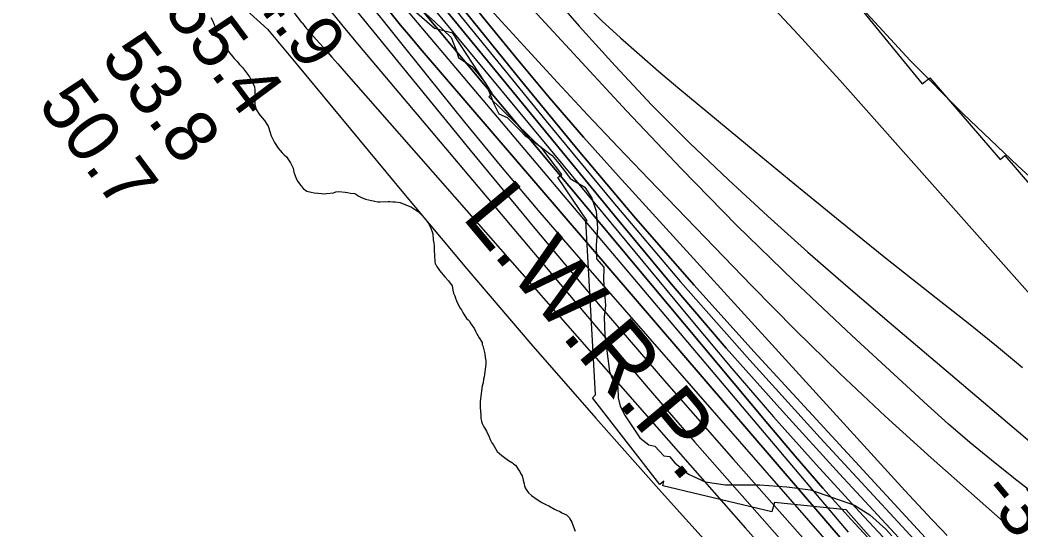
# Model space of a CAD drawing. Extents: x 3172231 to 3210228, y 940198 to 965780.
# Drawn here: x 3189862 to 3191136, y 947827 to 948476 of the extents above; entities that cross this region are included whole.
import ezdxf

# ---------------------------------------------------------------- set-up
doc = ezdxf.new("R2010")
doc.units = 0
for name, color, linetype in [('V-RIVR-EDGE', 7, 'Continuous'), ('V-RIVR-RANG', 7, 'Continuous'), ('V-RRAP-RVMT', 7, 'Continuous'), ('V-SITE-VEGE', 7, 'Continuous'), ('V-TOPO-DPTH', 7, 'Continuous'), ('V-TOPO-MAJR', 7, 'Continuous'), ('V-TOPO-MINR', 7, 'Continuous'), ('V-TOPO-WATR', 7, 'Continuous'), ('V-TOPO-WATR-IDEN', 7, 'Continuous')]:
    doc.layers.add(name, color=color, linetype=linetype)

msp = doc.modelspace()

# ---------------------------------------------------------------- linework, layer by layer
at = {"layer": 'V-RIVR-EDGE'}
msp.add_lwpolyline([(3190366.316, 948495.274), (3190390.12, 948473.951), (3190410.816, 948454.193), (3190416.484, 948439.139), (3190420.089, 948428.757), (3190437.175, 948417.305), (3190444.931, 948407.951), (3190454.754, 948395.48), (3190465.062, 948369.523), (3190471.255, 948357.061), (3190482.135, 948352.366), (3190499.205, 948334.691), (3190504.379, 948329.492), (3190513.18, 948323.247), (3190539.063, 948303.994), (3190547.854, 948293.599), (3190556.125, 948282.688), (3190562.328, 948274.375), (3190580.972, 948263.437), (3190589.753, 948249.413), (3190595.417, 948232.803), (3190596.921, 948211.536), (3190595.311, 948189.757), (3190595.786, 948172.123), (3190605.095, 948161.728), (3190604.536, 948145.133), (3190607.049, 948112.972), (3190605.456, 948097.936), (3190606.437, 948075.114), (3190612.028, 948028.943), (3190616.152, 948019.079), (3190622.869, 948008.69), (3190623.354, 947995.205), (3190625.921, 947984.826), (3190632.114, 947972.363), (3190650.715, 947944.312), (3190662.103, 947935.467), (3190669.878, 947933.892), (3190681.257, 947921.417), (3190688.515, 947920.362), (3190695.238, 947912.566), (3190712.835, 947898.001), (3190734.074, 947888.094), (3190759.996, 947884.4), (3190803.56, 947884.292), (3190837.784, 947882.133), (3190867.854, 947877.91), (3190923.817, 947858.582), (3190943.494, 947846.087), (3190963.675, 947827.885), (3190971.434, 947819.568)], dxfattribs=at)
at = {"layer": 'V-RRAP-RVMT'}
for p, q in [((3190389.336, 948465.465), (3190316.177, 948529.551)), ((3190928.391, 948495.235), (3191010.045, 948395.015)), ((3190413.033, 948459.827), (3190389.336, 948465.465)), ((3190462.729, 948383.048), (3190413.033, 948459.827)), ((3191010.045, 948395.015), (3191019.644, 948402.58)), ((3191019.644, 948402.58), (3191109.229, 948298.649)), ((3190458.678, 948378.482), (3190462.729, 948383.048)), ((3190527.429, 948311.44), (3190458.678, 948378.482)), ((3190551.491, 948279.665), (3190527.429, 948311.44)), ((3191109.229, 948298.649), (3191115.239, 948303.819)), ((3191115.239, 948303.819), (3191203.379, 948201.157)), ((3190546.232, 948275.951), (3190551.491, 948279.665)), ((3190583.935, 948220.607), (3190546.232, 948275.951)), ((3190594.437, 947999.217), (3190582.116, 948220.942)), ((3190582.116, 948220.942), (3190583.935, 948220.607)), ((3190590.752, 947995.233), (3190594.437, 947999.217)), ((3190676.421, 947884.906), (3190590.752, 947995.233)), ((3190681.229, 947889.042), (3190676.421, 947884.906)), ((3190680.041, 947883.411), (3190681.229, 947889.042)), ((3190818.891, 947849.985), (3190680.041, 947883.411)), ((3190822.343, 947861.93), (3190818.891, 947849.985)), ((3190913.183, 947852.785), (3190822.343, 947861.93)), ((3190998.585, 947756.725), (3190913.183, 947852.785))]:
    msp.add_line(p, q, dxfattribs=at)
at = {"layer": 'V-SITE-VEGE'}
for p, q in [((3190104.765, 948479.78), (3190106.871, 948475.696)), ((3190106.871, 948475.696), (3190108.949, 948470.511)), ((3190108.949, 948470.511), (3190110.305, 948465.71)), ((3190110.305, 948465.71), (3190113.4, 948456.83)), ((3190113.4, 948456.83), (3190114.448, 948454.604)), ((3190114.448, 948454.604), (3190117.608, 948448.661)), ((3190117.608, 948448.661), (3190121.881, 948443.058)), ((3190121.881, 948443.058), (3190132.938, 948429.59)), ((3190132.938, 948429.59), (3190134.353, 948427.353)), ((3190134.353, 948427.353), (3190138.299, 948423.593)), ((3190138.299, 948423.593), (3190141.515, 948419.848)), ((3190141.515, 948419.848), (3190145.095, 948416.096)), ((3190145.095, 948416.096), (3190153.987, 948404.146)), ((3190153.987, 948404.146), (3190157.147, 948398.2)), ((3190157.147, 948398.2), (3190160.301, 948391.89)), ((3190160.301, 948391.89), (3190160.915, 948386.74)), ((3190160.915, 948386.74), (3190160.768, 948380.505)), ((3190160.768, 948380.505), (3190161.03, 948376.096)), ((3190161.03, 948376.096), (3190160.858, 948368.76)), ((3190160.858, 948368.76), (3190162.546, 948362.485)), ((3190162.546, 948362.485), (3190166.443, 948356.523)), ((3190166.443, 948356.523), (3190170.371, 948352.028)), ((3190170.371, 948352.028), (3190173.22, 948348.292)), ((3190173.22, 948348.292), (3190175.342, 948344.942)), ((3190175.342, 948344.942), (3190177.822, 948341.215)), ((3190177.822, 948341.215), (3190180.199, 948333.086)), ((3190180.199, 948333.086), (3190181.574, 948329.019)), ((3190181.574, 948329.019), (3190183.327, 948325.676)), ((3190183.327, 948325.676), (3190185.772, 948320.481)), ((3190185.772, 948320.481), (3190190.378, 948313.403)), ((3190190.378, 948313.403), (3190195.74, 948307.406)), ((3190195.74, 948307.406), (3190198.246, 948304.779)), ((3190198.246, 948304.779), (3190201.12, 948302.145)), ((3190201.12, 948302.145), (3190206.447, 948294.682)), ((3190206.447, 948294.682), (3190209.582, 948287.637)), ((3190209.582, 948287.637), (3190210.563, 948282.478)), ((3190210.563, 948282.478), (3190211.585, 948279.152)), ((3190211.585, 948279.152), (3190213.316, 948274.706)), ((3190213.316, 948274.706), (3190215.787, 948270.614)), ((3190215.787, 948270.614), (3190218.984, 948266.135)), ((3190218.984, 948266.135), (3190219.699, 948265.385)), ((3190219.699, 948265.385), (3190222.548, 948261.65)), ((3190222.548, 948261.65), (3190227.244, 948258.606)), ((3190227.244, 948258.606), (3190232.71, 948257.009)), ((3190232.71, 948257.009), (3190236.362, 948256.188)), ((3190236.362, 948256.188), (3190245.887, 948255.598)), ((3190245.887, 948255.598), (3190248.078, 948255.178)), ((3190248.078, 948255.178), (3190252.119, 948255.45)), ((3190252.119, 948255.45), (3190260.946, 948256.343)), ((3190260.946, 948256.343), (3190263.905, 948257.376)), ((3190263.905, 948257.376), (3190267.59, 948258.023)), ((3190267.59, 948258.023), (3190275.638, 948257.099)), ((3190275.638, 948257.099), (3190278.931, 948256.655)), ((3190278.931, 948256.655), (3190282.581, 948255.836)), ((3190282.581, 948255.836), (3190287.705, 948255.348)), ((3190287.705, 948255.348), (3190288.797, 948254.957)), ((3190288.797, 948254.957), (3190290.247, 948254.189)), ((3190290.247, 948254.189), (3190292.411, 948252.671)), ((3190292.411, 948252.671), (3190296.761, 948250.365)), ((3190296.761, 948250.365), (3190301.851, 948248.412)), ((3190301.851, 948248.412), (3190309.141, 948246.407)), ((3190309.141, 948246.407), (3190313.524, 948245.569)), ((3190313.524, 948245.569), (3190317.176, 948244.75)), ((3190317.176, 948244.75), (3190320.483, 948245.038)), ((3190320.483, 948245.038), (3190330.394, 948245.174)), ((3190330.394, 948245.174), (3190332.601, 948245.489)), ((3190332.601, 948245.489), (3190336.626, 948245.026)), ((3190336.626, 948245.026), (3190339.56, 948244.957)), ((3190339.56, 948244.957), (3190345.776, 948244.078)), ((3190345.776, 948244.078), (3190360.307, 948237.866)), ((3190360.307, 948237.866), (3190365.369, 948234.813)), ((3190365.369, 948234.813), (3190368.619, 948232.533)), ((3190368.619, 948232.533), (3190371.849, 948229.523)), ((3190371.849, 948229.523), (3190373.633, 948227.28)), ((3190373.633, 948227.28), (3190378.278, 948222.033)), ((3190378.278, 948222.033), (3190381.485, 948217.923)), ((3190381.485, 948217.923), (3190384.995, 948211.236)), ((3190384.995, 948211.236), (3190386.726, 948206.792)), ((3190386.726, 948206.792), (3190387.398, 948204.21)), ((3190387.398, 948204.21), (3190387.951, 948196.493)), ((3190387.951, 948196.493), (3190388.598, 948192.806)), ((3190388.598, 948192.806), (3190389.228, 948188.391)), ((3190389.228, 948188.391), (3190389.167, 948185.823)), ((3190389.167, 948185.823), (3190389.626, 948174.071)), ((3190389.626, 948174.071), (3190389.933, 948171.497)), ((3190389.933, 948171.497), (3190389.88, 948169.295)), ((3190389.88, 948169.295), (3190390.535, 948165.98)), ((3190390.535, 948165.98), (3190391.244, 948164.861)), ((3190391.244, 948164.861), (3190392.292, 948162.635)), ((3190392.292, 948162.635), (3190395.837, 948157.417)), ((3190395.837, 948157.417), (3190402.614, 948149.186)), ((3190402.614, 948149.186), (3190407.269, 948144.306)), ((3190407.269, 948144.306), (3190411.892, 948137.961)), ((3190411.892, 948137.961), (3190412.862, 948132.435)), ((3190412.862, 948132.435), (3190413.868, 948128.374)), ((3190413.868, 948128.374), (3190415.257, 948125.04)), ((3190415.257, 948125.04), (3190416.287, 948122.081)), ((3190416.287, 948122.081), (3190417.675, 948118.744)), ((3190417.675, 948118.744), (3190421.87, 948109.842)), ((3190421.87, 948109.842), (3190423.643, 948107.233)), ((3190423.643, 948107.233), (3190425.048, 948104.632)), ((3190425.048, 948104.632), (3190426.813, 948101.656)), ((3190426.813, 948101.656), (3190430.361, 948096.436)), ((3190430.361, 948096.436), (3190432.517, 948094.549)), ((3190432.517, 948094.549), (3190433.94, 948092.682)), ((3190433.94, 948092.682), (3190434.997, 948090.822)), ((3190434.997, 948090.822), (3190440.318, 948082.992)), ((3190440.318, 948082.992), (3190441.715, 948080.025)), ((3190441.715, 948080.025), (3190442.755, 948077.432)), ((3190442.755, 948077.432), (3190446.284, 948071.479)), ((3190446.284, 948071.479), (3190450.179, 948065.515)), ((3190450.179, 948065.515), (3190450.128, 948063.317)), ((3190450.128, 948063.317), (3190450.818, 948061.466)), ((3190450.818, 948061.466), (3190453.519, 948051.496)), ((3190453.519, 948051.496), (3190454.14, 948046.712)), ((3190454.674, 948038.262), (3190452.819, 948021.794)), ((3190454.14, 948046.712), (3190454.779, 948042.661)), ((3190454.779, 948042.661), (3190454.674, 948038.262)), ((3190450.353, 948010.481), (3190447.689, 947990.73)), ((3190451.547, 948014.487), (3190450.353, 948010.481)), ((3190452.018, 948018.88), (3190451.547, 948014.487)), ((3190452.819, 948021.794), (3190452.018, 948018.88)), ((3190447.689, 947990.73), (3190447.506, 947983.03)), ((3190447.506, 947983.03), (3190448.129, 947978.245)), ((3190448.129, 947978.245), (3190448.367, 947972.736)), ((3190448.367, 947972.736), (3190448.278, 947969.07)), ((3190448.278, 947969.07), (3190449.292, 947965.38)), ((3190449.292, 947965.38), (3190450.333, 947962.783)), ((3190450.333, 947962.783), (3190451.365, 947959.826)), ((3190451.365, 947959.826), (3190453.136, 947957.215)), ((3190453.136, 947957.215), (3190455.6, 947952.754)), ((3190455.6, 947952.754), (3190459.104, 947945.703)), ((3190459.104, 947945.703), (3190460.493, 947942.367)), ((3190460.493, 947942.367), (3190462.59, 947937.912)), ((3190462.59, 947937.912), (3190464.013, 947936.046)), ((3190464.013, 947936.046), (3190465.768, 947932.704)), ((3190465.768, 947932.704), (3190469.307, 947927.117)), ((3190469.307, 947927.117), (3190475.052, 947921.846)), ((3190475.052, 947921.846), (3190476.86, 947920.703)), ((3190476.86, 947920.703), (3190483.707, 947915.405)), ((3190483.707, 947915.405), (3190488.772, 947912.351)), ((3190488.772, 947912.351), (3190490.572, 947910.842)), ((3190490.572, 947910.842), (3190492.378, 947909.699)), ((3190492.378, 947909.699), (3190496.273, 947903.737)), ((3190496.273, 947903.737), (3190498.055, 947901.493)), ((3190498.055, 947901.493), (3190499.454, 947898.525)), ((3190499.454, 947898.525), (3190500.863, 947895.924)), ((3190500.863, 947895.924), (3190502.198, 947890.388)), ((3190502.198, 947890.388), (3190503.552, 947885.588)), ((3190503.552, 947885.588), (3190503.859, 947883.011)), ((3190503.859, 947883.011), (3190504.908, 947880.785)), ((3190504.908, 947880.785), (3190506.323, 947878.553)), ((3190506.323, 947878.553), (3190509.161, 947874.449)), ((3190509.161, 947874.449), (3190512.741, 947870.697)), ((3190512.741, 947870.697), (3190519.963, 947865.757)), ((3190519.963, 947865.757), (3190526.111, 947861.944)), ((3190526.111, 947861.944), (3190531.184, 947859.257)), ((3190531.184, 947859.257), (3190534.817, 947857.702)), ((3190534.817, 947857.702), (3190542.054, 947853.498)), ((3190542.054, 947853.498), (3190545.679, 947851.579)), ((3190545.679, 947851.579), (3190548.596, 947850.776)), ((3190548.596, 947850.776), (3190551.485, 947848.873)), ((3190551.485, 947848.873), (3190557.658, 947846.16)), ((3190557.658, 947846.16), (3190561.24, 947842.408)), ((3190561.24, 947842.408), (3190561.58, 947841.298)), ((3190561.58, 947841.298), (3190564.41, 947836.829)), ((3190564.41, 947836.829), (3190565.084, 947834.244)), ((3190565.084, 947834.244), (3190568.543, 947825.358))]:
    msp.add_line(p, q, dxfattribs=at)
at = {"layer": 'V-TOPO-DPTH'}
for points in [[(3190956.043, 947800.747), (3190919.634, 947840.373), (3190883.674, 947880.397), (3190848.389, 947921.017), (3190813.553, 947962.034), (3190369.937, 948493.322), (3190346.753, 948521.468), (3190323.822, 948549.816), (3190301.271, 948578.467), (3190278.973, 948607.32), (3190243.332, 948654.081), (3190203.836, 948706.778), (3190164.916, 948759.889), (3190126.858, 948813.622), (3190089.376, 948867.77), (3189655.811, 949505.052)], [(3189655.811, 949505.052), (3190089.376, 948867.77), (3190126.858, 948813.622), (3190164.916, 948759.889), (3190203.836, 948706.778), (3190243.332, 948654.081), (3190278.973, 948607.32), (3190301.271, 948578.467), (3190323.822, 948549.816), (3190346.753, 948521.468), (3190369.937, 948493.322), (3190813.553, 947962.034), (3190848.389, 947921.017), (3190883.674, 947880.397), (3190919.634, 947840.373), (3190956.043, 947800.747)], [(3191003.798, 947703.104), (3190371.389, 948440.144), (3190358.843, 948454.937), (3190346.412, 948469.826), (3190334.153, 948484.856), (3190322.008, 948499.982), (3190300.709, 948526.825), (3190297.937, 948530.408), (3190296.588, 948532.227), (3190295.256, 948534.06), (3190168.365, 948711.421), (3190104.034, 948802.244), (3190040.277, 948893.464), (3189977.384, 948985.282), (3189915.067, 949077.497), (3189649.664, 949474.253)], [(3189835.656, 949342.933), (3189875.193, 949284.61), (3189915.335, 949226.69), (3190359.307, 948596.551), (3190364.024, 948589.98), (3190368.818, 948583.467), (3190373.727, 948577.041), (3190378.713, 948570.671), (3190451.359, 948479.548), (3190493.222, 948428.084), (3190535.747, 948377.184), (3190579.265, 948327.131), (3190623.446, 948277.642), (3190987.871, 947877.426), (3190999.332, 947864.938), (3191010.859, 947852.511), (3191022.483, 947840.176), (3191034.173, 947827.902), (3191041.949, 947819.8)], [(3191041.949, 947819.8), (3191034.173, 947827.902), (3191022.483, 947840.176), (3191010.859, 947852.511), (3190999.332, 947864.938), (3190987.871, 947877.426), (3190623.446, 948277.642), (3190579.265, 948327.131), (3190535.747, 948377.184), (3190493.222, 948428.084), (3190451.359, 948479.548), (3190378.713, 948570.671), (3190373.727, 948577.041), (3190368.818, 948583.467), (3190364.024, 948589.98), (3190359.307, 948596.551), (3189915.335, 949226.69), (3189875.193, 949284.61), (3189835.656, 949342.933)], [(3191023.364, 947770.724), (3190904.893, 947898.407), (3190832.346, 947978.08), (3190760.814, 948058.638), (3190690.804, 948140.522), (3190621.809, 948223.289), (3190373.515, 948526.887), (3190358.418, 948545.638), (3190343.515, 948564.539), (3190328.902, 948583.666), (3190314.483, 948602.943), (3190164.377, 948806.86), (3190075.773, 948928.719), (3189988.133, 949051.259), (3189901.938, 949174.82), (3189816.707, 949299.062)], [(3189816.707, 949299.062), (3189901.938, 949174.82), (3189988.133, 949051.259), (3190075.773, 948928.719), (3190164.377, 948806.86), (3190314.483, 948602.943), (3190328.902, 948583.666), (3190343.515, 948564.539), (3190358.418, 948545.638), (3190373.515, 948526.887), (3190621.809, 948223.289), (3190690.804, 948140.522), (3190760.814, 948058.638), (3190832.346, 947978.08), (3190904.893, 947898.407), (3191023.364, 947770.724)], [(3189861.87, 949268.627), (3190340.799, 948599.332), (3190349.481, 948587.412), (3190358.294, 948575.592), (3190367.304, 948563.922), (3190376.446, 948552.352), (3190500.175, 948398.426), (3190572.135, 948310.703), (3190645.234, 948223.96), (3190720.042, 948138.686), (3190795.989, 948054.391), (3191058.755, 947768.507)], [(3191058.755, 947768.507), (3190795.989, 948054.391), (3190720.042, 948138.686), (3190645.234, 948223.96), (3190572.135, 948310.703), (3190500.175, 948398.426), (3190376.446, 948552.352), (3190367.304, 948563.922), (3190358.294, 948575.592), (3190349.481, 948587.412), (3190340.799, 948599.332), (3189861.87, 949268.627)], [(3190461.032, 948489.491), (3190507.779, 948438.256), (3190546.009, 948396.702), (3190584.466, 948355.36), (3190623.263, 948314.337), (3190662.287, 948273.527), (3190793.168, 948137.78), (3190848.738, 948081.498), (3190905.176, 948026.12), (3190962.914, 947972.1), (3191021.518, 947918.984), (3191120.419, 947831.465), (3191130.389, 947823.002)], [(3190461.032, 948489.491), (3190507.779, 948438.256), (3190546.009, 948396.702), (3190584.466, 948355.36), (3190623.263, 948314.337), (3190662.287, 948273.527), (3190793.168, 948137.78), (3190848.738, 948081.498), (3190905.176, 948026.12), (3190962.914, 947972.1), (3191021.518, 947918.984), (3191120.419, 947831.465), (3191130.389, 947823.002)]]:
    msp.add_lwpolyline(points, dxfattribs=at)
at = {"layer": 'V-TOPO-MAJR'}
for points in [[(3191154.681, 947871.381), (3191126.651, 947893.029), (3191126.118, 947893.444), (3191098.181, 947915.734), (3191070.624, 947938.473), (3191043.637, 947961.886), (3191017.03, 947985.747), (3190920.418, 948074.564), (3190846.679, 948144.062), (3190774.125, 948214.745), (3190703.348, 948287.208), (3190633.756, 948360.857), (3190452.822, 948557.164), (3190428.905, 948583.887), (3190405.525, 948611.058), (3190382.949, 948638.901), (3190360.91, 948667.193), (3190318.117, 948723.816), (3190275.654, 948781.158), (3190233.951, 948839.037), (3190193.388, 948897.719), (3190153.584, 948956.938), (3189741.723, 949582.816)], [(3189572.544, 949441.368), (3189951.891, 948895.282), (3189999.909, 948827.269), (3190048.609, 948759.756), (3190098.331, 948692.992), (3190148.735, 948626.727), (3190211.647, 948545.313), (3190231.262, 948520.256), (3190251.084, 948495.367), (3190271.218, 948470.73), (3190291.559, 948446.259), (3190602.355, 948077.126), (3190661.339, 948007.74), (3190720.757, 947938.732), (3190780.826, 947870.291), (3190841.33, 947802.226)]]:
    msp.add_lwpolyline(points, dxfattribs=at)
at = {"layer": 'V-TOPO-MINR'}
for points in [[(3191241.524, 948190.066), (3191131.775, 948290.836), (3191062.425, 948356.998), (3190994.832, 948424.845), (3190929.877, 948495.222), (3190866.681, 948567.285), (3190694.76, 948771.046), (3190680.563, 948788.612), (3190666.877, 948806.551), (3190653.959, 948825.05), (3190641.553, 948843.923), (3190474.889, 949109.494), (3190401.466, 949228.592), (3190329.326, 949348.447), (3190259.109, 949469.439), (3190190.175, 949591.189), (3190069.133, 949809.008)], [(3189828.143, 949660.88), (3189971.35, 949440.608), (3190050.38, 949326.398), (3190133.575, 949215.505), (3190223.019, 949109.588), (3190316.628, 949006.987), (3190536.413, 948779.622), (3190556.317, 948759.184), (3190576.321, 948738.845), (3190596.476, 948718.656), (3190616.732, 948698.566), (3190688.372, 948628.036), (3190743.943, 948572.205), (3190798.743, 948515.642), (3190852.385, 948457.98), (3190905.255, 948399.586), (3191294.96, 947960.294)], [(3189658.098, 949517.424), (3189955.56, 949079.272), (3190016.527, 948990.791), (3190078.298, 948902.883), (3190141.276, 948815.836), (3190205.059, 948729.363), (3190298.1, 948605.031), (3190316.135, 948581.287), (3190334.395, 948557.721), (3190352.993, 948534.419), (3190371.815, 948511.294), (3190715.668, 948094.983), (3190767.997, 948032.766), (3190821.055, 947971.186), (3190875.203, 947910.564), (3190930.078, 947850.58), (3191003.325, 947771.936)], [(3189653.537, 949492.693), (3190218.667, 948663.708), (3190233.348, 948642.604), (3190248.29, 948621.691), (3190263.623, 948601.063), (3190279.219, 948580.626), (3190295.131, 948560.43), (3190311.205, 948540.365), (3190327.521, 948520.496), (3190343.998, 948500.758), (3190915.826, 947824.144)], [(3189649.664, 949474.253), (3189915.067, 949077.497), (3189977.384, 948985.282), (3190040.277, 948893.464), (3190104.034, 948802.244), (3190168.365, 948711.421), (3190295.256, 948534.06), (3190296.588, 948532.227), (3190297.937, 948530.408), (3190300.709, 948526.825), (3190322.008, 948499.982), (3190334.153, 948484.856), (3190346.412, 948469.826), (3190358.843, 948454.937), (3190371.389, 948440.144), (3191003.798, 947703.104)], [(3189850.17, 949448.95), (3189906.574, 949364.75), (3189963.712, 949281.058), (3190021.95, 949198.129), (3190080.922, 949115.708), (3190411.126, 948660.591), (3190422.001, 948646.01), (3190433.125, 948631.627), (3190444.625, 948617.543), (3190456.374, 948603.656), (3190573.673, 948468.665), (3190619.269, 948417.877), (3190665.923, 948368.113), (3190714.164, 948319.886), (3190763.463, 948272.683), (3190813.859, 948226.591), (3190864.659, 948180.954), (3190916.063, 948136), (3190967.87, 948091.5), (3191199.717, 947895.029)], [(3189654.756, 949405.366), (3190276.246, 948537.001), (3190281.623, 948529.611), (3190287.075, 948522.279), (3190292.642, 948515.033), (3190298.284, 948507.844), (3190380.452, 948404.824), (3190427.618, 948346.486), (3190475.293, 948288.575), (3190523.733, 948231.301), (3190572.682, 948174.452), (3190982.548, 947704.784), (3190988.103, 947698.499), (3190993.711, 947692.263), (3190999.397, 947686.099), (3191005.137, 947679.982), (3191821.886, 947045.773), (3191936.602, 946961.604), (3191956.768, 946945.504), (3191975.964, 946928.401), (3191993.708, 946909.795), (3192010.483, 946890.186), (3192012.814, 946887.224)], [(3189835.656, 949342.933), (3189875.193, 949284.61), (3189915.335, 949226.69), (3190359.307, 948596.551), (3190364.024, 948589.98), (3190368.818, 948583.467), (3190373.727, 948577.041), (3190378.713, 948570.671), (3190451.359, 948479.548), (3190493.222, 948428.084), (3190535.747, 948377.184), (3190579.265, 948327.131), (3190623.446, 948277.642), (3190987.871, 947877.426), (3190999.332, 947864.938), (3191010.859, 947852.511), (3191022.483, 947840.176), (3191034.173, 947827.902), (3191041.949, 947819.8)], [(3189816.707, 949299.062), (3189901.938, 949174.82), (3189988.133, 949051.259), (3190075.773, 948928.719), (3190164.377, 948806.86), (3190314.483, 948602.943), (3190328.902, 948583.666), (3190343.515, 948564.539), (3190358.418, 948545.638), (3190373.515, 948526.887), (3190621.809, 948223.289), (3190690.804, 948140.522), (3190760.814, 948058.638), (3190832.346, 947978.08), (3190904.893, 947898.407), (3191023.364, 947770.724)], [(3189271.701, 949283.317), (3190177.18, 948464.824), (3190189.741, 948449.425), (3190202.355, 948434.07), (3190215.004, 948418.744), (3190349.973, 948255.782), (3190430.715, 948159.499), (3190512.233, 948063.886), (3190594.915, 947969.277), (3190678.373, 947875.339), (3190859.895, 947673.523), (3190883.501, 947646.818), (3190906.794, 947619.848), (3190929.619, 947592.48), (3190952.131, 947564.847), (3191055.723, 947435.429)], [(3189831.843, 949292.906), (3189892.729, 949205.034), (3189954.486, 949117.772), (3190016.823, 949030.916), (3190328.594, 948601.048), (3190339.925, 948585.686), (3190351.418, 948570.45), (3190363.155, 948555.4), (3190375.055, 948540.474), (3190531.459, 948347.503), (3190616.398, 948244.76), (3190702.639, 948143.146), (3190790.836, 948043.224), (3190880.337, 947944.43), (3191041.855, 947769.581)], [(3189861.87, 949268.627), (3190340.799, 948599.332), (3190349.481, 948587.412), (3190358.294, 948575.592), (3190367.304, 948563.922), (3190376.446, 948552.352), (3190500.175, 948398.426), (3190572.135, 948310.703), (3190645.234, 948223.96), (3190720.042, 948138.686), (3190795.989, 948054.391), (3191058.755, 947768.507)], [(3189726.179, 949118.6), (3190220.44, 948473.312), (3190220.888, 948472.734), (3190221.342, 948472.162), (3190224.465, 948468.273), (3190226.272, 948466.057), (3190228.1, 948463.86), (3190229.961, 948461.69), (3190231.843, 948459.538), (3190243.425, 948446.5), (3190251.107, 948437.837), (3190258.778, 948429.164), (3190266.435, 948420.478), (3190274.081, 948411.783), (3190785.394, 947829.287), (3190811.718, 947799.441), (3190838.135, 947769.678), (3190864.693, 947740.041), (3190891.344, 947710.487), (3190918.132, 947681.057), (3190945.008, 947651.708), (3190972.017, 947622.481), (3190999.115, 947593.336), (3191258.344, 947315.778)], [(3189852.346, 949080.564), (3189926.591, 948977.784), (3190001.525, 948875.495), (3190249.344, 948540.735), (3190260.572, 948525.792), (3190271.939, 948510.958), (3190283.517, 948496.288), (3190295.235, 948481.726), (3190435.024, 948310.519), (3190517.334, 948210.94), (3190600.435, 948112.032), (3190684.72, 948014.132), (3190769.795, 947916.905), (3190955.962, 947706.712)], [(3190579.392, 948497.8), (3190602.536, 948475.476), (3190626.284, 948453.761), (3190650.269, 948432.315), (3190674.609, 948411.273), (3190699.187, 948390.5), (3190790.423, 948314.685), (3190847.846, 948267.337), (3190905.509, 948220.285), (3190963.53, 948173.675), (3191021.789, 948127.36), (3191070.951, 948088.584), (3191104.535, 948061.554), (3191137.755, 948034.092)], [(3190461.032, 948489.491), (3190507.779, 948438.256), (3190546.009, 948396.702), (3190584.466, 948355.36), (3190623.263, 948314.337), (3190662.287, 948273.527), (3190793.168, 948137.78), (3190848.738, 948081.498), (3190905.176, 948026.12), (3190962.914, 947972.1), (3191021.518, 947918.984), (3191120.419, 947831.465), (3191130.389, 947823.002)]]:
    msp.add_lwpolyline(points, dxfattribs=at)
at = {"layer": 'V-TOPO-WATR'}
msp.add_lwpolyline([(3189655.811, 949505.052), (3190089.376, 948867.77), (3190126.858, 948813.622), (3190164.916, 948759.889), (3190203.836, 948706.778), (3190243.332, 948654.081), (3190278.973, 948607.32), (3190301.271, 948578.467), (3190323.822, 948549.816), (3190346.753, 948521.468), (3190369.937, 948493.322), (3190813.553, 947962.034), (3190848.389, 947921.017), (3190883.674, 947880.397), (3190919.634, 947840.373), (3190956.043, 947800.747)], dxfattribs=at)

# ---------------------------------------------------------------- texts
at = {"layer": 'V-RIVR-RANG'}
for s, rotation, p in [('44.9', 306.678326, (3190123.541, 948548.564)), ('55.4', 306.678326, (3190043.642, 948488.427)), ('53.8', 306.678326, (3189963.587, 948428.502)), ('50.7', 306.678326, (3189883.531, 948368.576)), ('-30', 309.871667, (3191081.34, 947872.962))]:
    msp.add_text(s, height=67, rotation=rotation, dxfattribs=at).set_placement(p)
at = {"layer": 'V-TOPO-WATR-IDEN'}
msp.add_text('L.W.R.P.', height=83, rotation=309.926449, dxfattribs=at).set_placement((3190422.994, 948225.563))

doc.saveas('drawing.dxf')
